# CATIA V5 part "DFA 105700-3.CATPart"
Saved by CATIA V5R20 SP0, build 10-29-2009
Part number: DFA 105700-3
Revision: ANY
Definition: UNKNOWN
Nomenclature: DFA 105700-3
Source: Unknown
Bounding box of the stored display mesh (mm): x -2.687 to 2.687, y -2.475 to 2.475, z -2.5 to 2.5
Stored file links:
  C:\Users\Utente\Desktop\IO LAVORO\3D X SITO CF\CUMSA\3D files FA\FA 105706-21\DFA 105700-3.CATPart
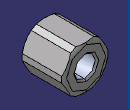
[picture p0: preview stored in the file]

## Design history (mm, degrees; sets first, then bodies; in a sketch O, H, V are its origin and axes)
Body1 "Chaflán4" (main body)
  Solid1: solid without history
